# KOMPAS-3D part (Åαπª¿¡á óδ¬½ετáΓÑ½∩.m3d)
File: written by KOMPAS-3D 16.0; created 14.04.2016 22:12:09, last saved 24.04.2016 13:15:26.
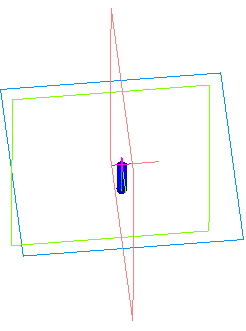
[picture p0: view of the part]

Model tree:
1. Эскиз:1
2. Спираль цилиндрическая:1
     Число витков = 18; Шаг = 0.5; Высота = 9; Диаметр 1 = 2; Диаметр 2 = 10
3. Эскиз:2
4. Кинематическая операция:1
5. Ось пересечения двух плоскостей:2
